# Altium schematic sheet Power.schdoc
size 297 x 209 mm; Symbol: Drawing-Symbol_A4; Company: 嘉立创EDA; Version: V1.0; Page Size: A4; @Project Name: 远程开机卡; @Update Date: 2026-05-20; @Create Date: 2026-05-20; Device: Drawing-Symbol_A4; @Board Name: cm4; @Page Name: P1; @Create Time: 23:55:36; @Page Count: 5; @Page No: 5; @Schematic Name: Schematic3_7; @Update Time: 23:55:36; @Assembly Variant: Basic; Border: 1; Title Block Position: 3; Size: A4; Width: 1170; Height: 825; Region Start: 1; X Region Count: 6; Y Region Count: 4; Blade Width: 10
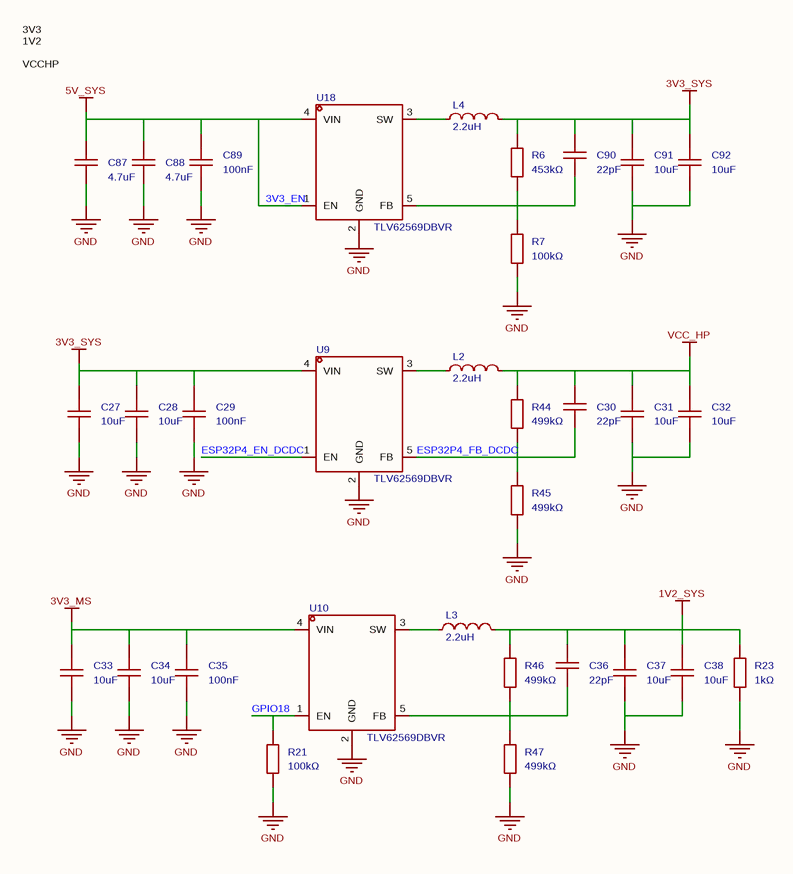
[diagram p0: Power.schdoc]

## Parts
C27  10uF  [C0805]
C28  10uF  [C0805]
C29  100nF  [C0603]
C30  22pF  [C0402]
C31  10uF  [C0805]
C32  10uF  [C0805]
C33  10uF  [C0805]
C34  10uF  [C0805]
C35  100nF  [C0603]
C36  22pF  [C0402]
C37  10uF  [C0805]
C38  10uF  [C0805]
C87  4.7uF  [C0805]
C88  4.7uF  [C0805]
C89  100nF  [C0603]
C90  22pF  [C0402]
C91  10uF  [C0805]
C92  10uF  [C0805]
L2  2.2uH  [IND-SMD_L3.0-W3.0_FNR30XXS]
L3  2.2uH  [IND-SMD_L3.0-W3.0_FNR30XXS]
L4  2.2uH  [IND-SMD_L3.0-W3.0_FNR30XXS]
R6  453kΩ  [R0603]
R7  100kΩ  [R0603]
R21  100kΩ  [R0603]
R23  1kΩ  [R0603]
R44  499kΩ  [R0603]
R45  499kΩ  [R0603]
R46  499kΩ  [R0603]
R47  499kΩ  [R0603]
U9  TLV62569DBVR  [SOT-23-5_L3.0-W1.7-P0.95-LS2.8-BR]
U10  TLV62569DBVR  [SOT-23-5_L3.0-W1.7-P0.95-LS2.8-BR]
U18  TLV62569DBVR  [SOT-23-5_L3.0-W1.7-P0.95-LS2.8-BR]

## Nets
1V2_SYS: C36.2 C37.2 C38.2 L3.2 R23.2 R46.2
3V3_EN: C87.2 C88.2 C89.2 U18.1(EN) U18.4(VIN)  [also labelled 5V_SYS]
3V3_MS: C33.2 C34.2 C35.2 U10.4(VIN)
3V3_SYS: C27.2 C28.2 C29.2 C90.2 C91.2 C92.2 L4.2 R6.2 U9.4(VIN)
GND: C27.1 C28.1 C29.1 C31.1 C32.1 C33.1 C34.1 C35.1 C37.1 C38.1 C87.1 C88.1 C89.1 C91.1 C92.1 R7.1 R21.1 R23.1 R45.1 R47.1 U9.2(GND) U10.2(GND) U18.2(GND)
VCC_HP: C30.2 C31.2 C32.2 L2.2 R44.2
ESP32P4_EN_DCDC: U9.1(EN)
ESP32P4_FB_DCDC: C30.1 R44.1 R45.2 U9.5(FB)
GPIO18: R21.2 U10.1(EN)
NetC36_1: C36.1 R46.1 R47.2 U10.5(FB)
NetC90_1: C90.1 R6.1 R7.2 U18.5(FB)
NetL2_1: L2.1 U9.3(SW)
NetL3_1: L3.1 U10.3(SW)
NetL4_1: L4.1 U18.3(SW)

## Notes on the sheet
- 3V3
  1V2
  VCCHP

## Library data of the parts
C27 C28 C31-C34 C37 C38 C91 C92 = CL21A106KAYNNNE_C15850: 容值:10uF;精度:±10%;额定电压:25V;温度系数:X5R;; Manufacturer: SAMSUNG(三星); Add into BOM: yes; 3D Model: 1ba041120af144c991958decab20d241; 3D Model Transform: 78.74,51.181,0,0,0,0,0,0.0005,0; Tolerance: ±10%; Voltage Rating: 25V; Temperature Coefficient: X5R; ModelName: C0805_L2.0-W1.3-H1.3
C29 C35 C89 = CC0603KRX7R9BB104: 容值:100nF;精度:±10%;额定电压:50V;温度系数:X7R;; Manufacturer: YAGEO(国巨); Add into BOM: yes; 3D Model: ac125912035d415993ca9572d50418b1; 3D Model Transform: 62.992,31.496,0,0,0,0,0,0,0; Tolerance: ±10%; Voltage Rating: 50V; Temperature Coefficient: X7R; ModelName: C0603_L1.6-W0.8-H0.8
C30 C36 C90 = 0402CG220J500NT: 容值:22pF;精度:±5%;额定电压:50V;温度系数:C0G;; Manufacturer: FH(风华); Add into BOM: yes; 3D Model: 36a51122f27c49738f86b3bfa98863e0; 3D Model Transform: 39.37,19.685,0,0,0,0,0,0,0; Tolerance: ±5%; Voltage Rating: 50V; Temperature Coefficient: C0G; ModelName: C0402_L1.0-W0.5-H0.5
C87 C88 = CL21A475KAQNNNE: 容值:4.7uF;精度:±10%;额定电压:25V;温度系数:X5R;; Manufacturer: SAMSUNG(三星); Add into BOM: yes; 3D Model: 1ba041120af144c991958decab20d241; 3D Model Transform: 78.74,51.181,0,0,0,0,0,0.0005,0; Tolerance: ±10%; Voltage Rating: 25V; Temperature Coefficient: X5R; ModelName: C0805_L2.0-W1.3-H1.3
L2-L4 = FNR3015S2R2MT: 电感值:2.2uH;精度:±20%;额定电流:2A;饱和电流(Isat):2A;类型:磁胶屏蔽电感;; Manufacturer: cjiang(长江微电); Add into BOM: yes; 3D Model: 822d71758aa744dca2559abd61137eb2; Tolerance: ±20%; Type: 磁胶屏蔽电感; 3D Model Transform: 118.11,118.11,0,90,0,0,0,0,0; Current - Saturation(Isat): 2A; DC Resistance(DCR): 78mΩ; ModelName: IND-SMD_L3.0-W3.0-H1.5_FNR30XXS
R6 = FRC0603F4533TS: 电阻类型:厚膜电阻;阻值:453kΩ;精度:±1%;功率:100mW;工作电压:75V;温度系数:±100ppm/℃;; Manufacturer: FOJAN(富捷); Symbol: 电阻; Add into BOM: yes; 3D Model: fc143cca1e79419f9cd78b61e9279f080819f05c4eef4c71ace90d822a990e87; 3D Model Transform: 31.8897,63.7794,0,90,0,0,0,0,0; Tolerance: ±1%; Power(Watts): 100mW; Voltage-Supply(Max): 75V
R7 R21 = 0603WAF1003T5E: 电阻类型:厚膜电阻;阻值:100kΩ;精度:±1%;功率:100mW;工作电压:75V;温度系数:±100ppm/℃;; Manufacturer: UNI-ROYAL(厚声); Add into BOM: yes; 3D Model: fc143cca1e79419f9cd78b61e9279f08; 3D Model Transform: 31.8897,63.7794,0,90,0,0,0,0,0; Tolerance: ±1%; Power(Watts): 100mW; Voltage-Supply(Max): 75V
R23 = 0603WAF1001T5E: 电阻类型:厚膜电阻;阻值:1kΩ;精度:±1%;功率:100mW;工作电压:75V;温度系数:±100ppm/℃;; Manufacturer: UNI-ROYAL(厚声); Add into BOM: yes; 3D Model: fc143cca1e79419f9cd78b61e9279f08; 3D Model Transform: 31.8897,63.7794,0,90,0,0,0,0,0; Tolerance: ±1%; Power(Watts): 100mW; Voltage-Supply(Max): 75V
R44-R47 = FRC0603F4993TS: 电阻类型:厚膜电阻;阻值:499kΩ;精度:±1%;功率:100mW;工作电压:75V;温度系数:±100ppm/℃;; Manufacturer: FOJAN(富捷); Add into BOM: yes; Symbol: 电阻; 3D Model Transform: 31.8897,63.7794,0,90,0,0,0,0,0; Tolerance: ±1%; Power(Watts): 100mW; Voltage-Supply(Max): 75V; 3D Model: fc143cca1e79419f9cd78b61e9279f080819f05c4eef4c71ace90d822a990e87
U9 U10 = TLV62569DBVR: 功能类型:降压型;工作电压:2.5V~5.5V;输出电压:600mV~5.5V;输出电流:2A;输出类型:可调;; Manufacturer: TI(德州仪器); AddInBom: yes; ModelId: 0a2a1b8f50944f73965918ad6e5fe1670819f05c4eef4c71ace90d822a990e87; ModelName: SOT-23-5_L2.9-W1.6-H1.1-LS2.8-P0.95; ModelTransform: 114.173,109.636,0,180,0,0,0,0,0; Function: 降压型; Output Current: 2A; Frequency - Switching: 1.5MHz; Synchronous Rectifier: 是; Number of Outputs: 1; Topology: 降压式; Quiescent Current: 35uA; Switch tube (built-in/external): 内置; Output Type: 可调
U18 = TLV62569DBVR: 功能类型:降压型;工作电压:2.5V~5.5V;输出电压:600mV~5.5V;输出电流:2A;输出类型:可调;; Manufacturer: TI(德州仪器); 3D Model: 0a2a1b8f50944f73965918ad6e5fe1670819f05c4eef4c71ace90d822a990e87; 3D Model Transform: 114.173,109.636,0,180,0,0,0,0,0; Function: 降压型; Output Current: 2A; Frequency - Switching: 1.5MHz; Synchronous Rectifier: 是; Number of Outputs: 1; Topology: 降压式; Quiescent Current: 35uA; Switch tube (built-in/external): 内置; Output Type: 可调; AddInBom: yes; ModelName: SOT-23-5_L2.9-W1.6-H1.1-LS2.8-P0.95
